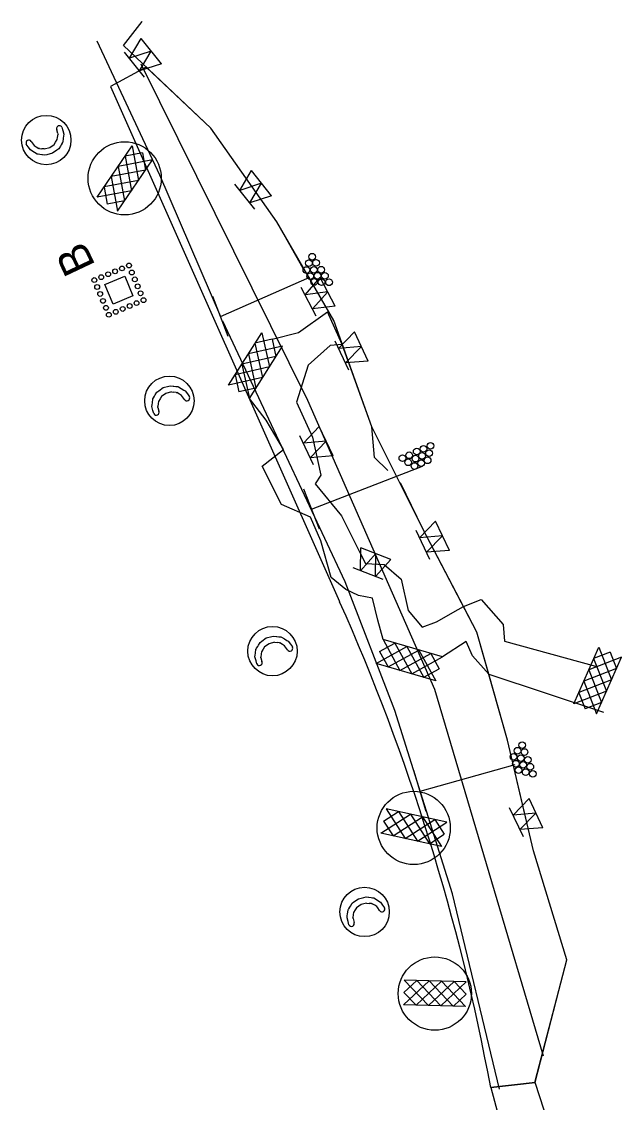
# Model space of a CAD drawing. Extents: x 400935 to 481562, y 415700 to 505362.
# Drawn here: x 477725 to 478005, y 499056 to 499559 of the extents above; entities that cross this region are included whole.
import ezdxf

# ---------------------------------------------------------------- set-up
doc = ezdxf.new("R2010")
doc.units = 0
for name, color, linetype in [('Coir Fiber Wattle with PAM Final CELL', 7, 'Continuous'), ('Drain Terminator Final CELL', 7, 'Continuous'), ('Earth Berm for Slope Drains Final', 7, 'Continuous'), ('Excelsior Wattle Line Style Final', 7, 'Continuous'), ('Label B Final CELL', 7, 'Continuous'), ('Matting on Slope Note Final CELL', 7, 'Continuous'), ('Rock Inlet Sediment Trap Type B Final CELL', 7, 'Continuous'), ('Rock Silt Check Type A CG CELL', 7, 'Continuous'), ('Rock Silt Check Type A Final CELL', 7, 'Continuous'), ('Rock Silt Check Type A with Matting and PAM CG CELL', 7, 'Continuous'), ('Slope Drain Final', 7, 'Continuous'), ('Slope Drain Inlet Final CELL', 7, 'Continuous'), ('Special Sediment Control Fence Section Both CELL', 7, 'Continuous'), ('Special Sediment Control Fence Section CG CELL', 7, 'Continuous'), ('Special Sediment Control Fence Section Final CELL', 7, 'Continuous'), ('Temporary Silt Fence Both', 7, 'Continuous'), ('Temporary Silt Fence CG', 7, 'Continuous'), ('Temporary Silt Fence Final', 7, 'Continuous')]:
    doc.layers.add(name, color=color, linetype=linetype)

msp = doc.modelspace()

# ---------------------------------------------------------------- linework, layer by layer
at = {"layer": 'Coir Fiber Wattle with PAM Final CELL'}
for p, q in [((477742.19, 499507), (477741.72, 499508.8)), ((477742.08, 499505.21), (477742.27, 499506.68)), ((477742.19, 499507), (477742.27, 499506.68)), ((477729.81, 499503.34), (477730.71, 499502.08)), ((477730.71, 499502.08), (477731.17, 499501.44)), ((477738.42, 499500.51), (477740.51, 499501.97)), ((477740.51, 499501.97), (477741.16, 499502.98)), ((477741.16, 499502.98), (477741.94, 499504.2)), ((477741.94, 499504.2), (477742.08, 499505.21)), ((477731.17, 499501.44), (477732.11, 499500.86)), ((477732.11, 499500.86), (477733.35, 499500.11)), ((477733.59, 499500.08), (477733.35, 499500.11)), ((477733.59, 499500.08), (477734.69, 499499.95)), ((477735.87, 499499.82), (477734.69, 499499.95)), ((477735.87, 499499.82), (477738.41, 499500.51)), ((477738.42, 499500.51), (477738.41, 499500.51)), ((477792.52, 499386.1), (477790.43, 499384.64)), ((477792.52, 499386.1), (477792.53, 499386.1)), ((477795.06, 499386.79), (477792.53, 499386.1)), ((477795.06, 499386.79), (477796.25, 499386.66)), ((477797.35, 499386.53), (477796.25, 499386.66)), ((477797.35, 499386.53), (477797.58, 499386.5)), ((477798.83, 499385.75), (477797.58, 499386.5)), ((477788.86, 499381.4), (477788.67, 499379.93)), ((477788.99, 499382.41), (477788.86, 499381.4)), ((477789.78, 499383.63), (477788.99, 499382.41)), ((477790.43, 499384.64), (477789.78, 499383.63)), ((477799.77, 499385.17), (477798.83, 499385.75)), ((477800.23, 499384.53), (477799.77, 499385.17)), ((477801.13, 499383.27), (477800.23, 499384.53)), ((477788.75, 499379.61), (477788.67, 499379.93)), ((477788.75, 499379.61), (477789.22, 499377.8)), ((477843.06, 499270.32), (477840.52, 499269.63)), ((477843.06, 499270.32), (477844.25, 499270.19)), ((477836.99, 499265.94), (477836.86, 499264.93)), ((477837.78, 499267.16), (477836.99, 499265.94)), ((477838.43, 499268.17), (477837.78, 499267.16)), ((477840.51, 499269.63), (477838.43, 499268.17)), ((477840.51, 499269.63), (477840.52, 499269.63)), ((477845.35, 499270.06), (477844.25, 499270.19)), ((477845.35, 499270.06), (477845.58, 499270.03)), ((477846.82, 499269.28), (477845.58, 499270.03)), ((477847.77, 499268.7), (477846.82, 499269.28)), ((477848.23, 499268.06), (477847.77, 499268.7)), ((477849.13, 499266.8), (477848.23, 499268.06)), ((477836.86, 499264.93), (477836.67, 499263.46)), ((477836.75, 499263.14), (477836.67, 499263.46)), ((477836.75, 499263.14), (477837.22, 499261.34)), ((477880.64, 499145.82), (477879.86, 499144.61)), ((477881.3, 499146.83), (477880.64, 499145.82)), ((477883.38, 499148.29), (477881.3, 499146.83)), ((477883.38, 499148.29), (477883.39, 499148.29)), ((477885.93, 499148.98), (477883.39, 499148.29)), ((477885.93, 499148.98), (477887.11, 499148.85)), ((477888.22, 499148.72), (477887.11, 499148.85)), ((477888.22, 499148.72), (477888.45, 499148.69)), ((477889.69, 499147.94), (477888.45, 499148.69)), ((477890.63, 499147.37), (477889.69, 499147.94)), ((477891.09, 499146.72), (477890.63, 499147.37)), ((477891.99, 499145.46), (477891.09, 499146.72)), ((477879.72, 499143.59), (477879.53, 499142.12)), ((477879.62, 499141.8), (477879.53, 499142.12)), ((477879.62, 499141.8), (477880.08, 499140)), ((477879.86, 499144.61), (477879.72, 499143.59))]:
    msp.add_line(p, q, dxfattribs=at)
for points in [[(477744.07, 499509.91), (477744.48, 499508.41), (477744.96, 499506.66), (477744.86, 499505.83), (477744.73, 499504.83), (477744.5, 499503.05), (477744.48, 499503.01), (477744.25, 499502.64), (477744.21, 499502.57), (477743.71, 499501.76), (477743.36, 499501.19), (477742.6, 499499.94), (477741.75, 499499.33), (477739.69, 499497.83), (477739.68, 499497.82), (477737.13, 499497.16), (477736.13, 499496.91), (477735.01, 499497.07), (477734.78, 499497.1), (477733.82, 499497.24), (477733.1, 499497.34), (477732.93, 499497.37), (477732.57, 499497.42), (477732.56, 499497.42), (477731.28, 499498.22), (477730.14, 499498.93), (477729.45, 499499.36), (477728.41, 499500.78), (477727.5, 499502.03)], [(477786.87, 499376.7), (477786.46, 499378.2), (477785.97, 499379.95), (477786.08, 499380.78), (477786.21, 499381.78), (477786.44, 499383.56), (477786.46, 499383.6), (477786.69, 499383.97), (477786.73, 499384.04), (477787.23, 499384.85), (477787.57, 499385.42), (477788.34, 499386.67), (477789.18, 499387.28), (477791.25, 499388.78), (477791.26, 499388.79), (477793.81, 499389.45), (477794.81, 499389.7), (477795.93, 499389.54), (477796.16, 499389.51), (477797.11, 499389.37), (477797.84, 499389.27), (477798, 499389.24), (477798.37, 499389.19), (477798.38, 499389.19), (477799.66, 499388.39), (477800.8, 499387.68), (477801.48, 499387.25), (477802.52, 499385.83), (477803.44, 499384.58)], [(477834.87, 499260.23), (477834.45, 499261.73), (477833.97, 499263.48), (477834.08, 499264.31), (477834.21, 499265.31), (477834.43, 499267.09), (477834.45, 499267.13), (477834.69, 499267.5), (477834.72, 499267.57), (477835.22, 499268.38), (477835.57, 499268.95), (477836.34, 499270.2), (477837.18, 499270.81), (477839.24, 499272.31), (477839.25, 499272.32), (477841.81, 499272.98), (477842.8, 499273.23), (477843.92, 499273.07), (477844.16, 499273.04), (477845.11, 499272.9), (477845.83, 499272.8), (477846, 499272.77), (477846.37, 499272.72), (477846.37, 499272.72), (477847.66, 499271.92), (477848.8, 499271.21), (477849.48, 499270.78), (477850.52, 499269.36), (477851.44, 499268.12)], [(477877.73, 499138.89), (477877.32, 499140.39), (477876.84, 499142.14), (477876.94, 499142.97), (477877.07, 499143.98), (477877.3, 499145.75), (477877.32, 499145.79), (477877.55, 499146.17), (477877.59, 499146.23), (477878.09, 499147.05), (477878.44, 499147.61), (477879.21, 499148.86), (477880.05, 499149.48), (477882.11, 499150.97), (477882.12, 499150.98), (477884.67, 499151.64), (477885.67, 499151.9), (477886.79, 499151.74), (477887.03, 499151.7), (477887.98, 499151.56), (477888.7, 499151.46), (477888.87, 499151.43), (477889.23, 499151.38), (477889.24, 499151.38), (477890.52, 499150.58), (477891.66, 499149.87), (477892.35, 499149.44), (477893.39, 499148.03), (477894.31, 499146.78)]]:
    msp.add_lwpolyline(points, dxfattribs=at)
for centre in [(477736.81, 499503.96), (477794.13, 499382.65), (477842.12, 499266.18), (477884.99, 499144.85)]:
    msp.add_circle(centre, 11.5, dxfattribs=at)
for centre, radius, start, end in [((477742.89, 499509.36), 1.3, 25.2938, 205.2938), ((477728.7, 499502.6), 1.33, 34.1812, 205.2938), ((477802.23, 499384.01), 1.33, 214.1812, 25.2938), ((477788.04, 499377.25), 1.3, 205.2938, 25.2938), ((477850.23, 499267.54), 1.33, 214.1812, 25.2938), ((477836.04, 499260.78), 1.3, 205.2938, 25.2938), ((477893.1, 499146.21), 1.33, 214.1812, 25.2938), ((477878.91, 499139.44), 1.3, 205.2938, 25.2938)]:
    msp.add_arc(centre, radius, start, end, dxfattribs=at)
at = {"layer": 'Drain Terminator Final CELL'}
for centre in [(477859.1, 499446.68), (477860.57, 499449.7), (477862.38, 499446.83), (477857.89, 499443.5), (477859.71, 499440.63), (477861.36, 499443.61), (477863.11, 499440.85), (477864.72, 499443.64), (477866.54, 499440.77), (477861.57, 499437.95), (477865, 499437.87), (477868.43, 499437.79), (477912.41, 499360.35), (477915.67, 499361.69), (477902.58, 499356.01), (477905.72, 499357.3), (477908.72, 499355.74), (477909.26, 499359.06), (477911.73, 499356.99), (477914.33, 499354.97), (477915, 499358.33), (477905.3, 499354.04), (477908.22, 499352.31), (477911.36, 499353.6), (477956.23, 499219.85), (477958.33, 499222.46), (477959.46, 499219.26), (477954.33, 499217.03), (477955.46, 499213.82), (477957.74, 499216.35), (477961.02, 499215.63), (477956.67, 499210.79), (477958.82, 499213.27), (477959.99, 499209.94), (477962.14, 499212.42), (477963.31, 499209.09)]:
    msp.add_circle(centre, 1.55, dxfattribs=at)
at = {"layer": 'Earth Berm for Slope Drains Final'}
for points in [[(477760.4, 499550.06), (477789.53, 499487.76), (477817.9, 499421.86)], [(477947.85, 499062.34), (477925.9, 499153.21), (477899.15, 499238.55), (477875.99, 499298.44), (477838.06, 499379.1), (477818.98, 499419.67)]]:
    msp.add_lwpolyline(points, dxfattribs=at)
at = {"layer": 'Excelsior Wattle Line Style Final'}
msp.add_lwpolyline([(477968.25, 499077.76), (477917.71, 499248.4), (477858.51, 499382.83), (477781.01, 499539.35)], dxfattribs=at)
at = {"layer": 'Matting on Slope Note Final CELL'}
for p, q in [((477783.38, 499537.83), (477766.68, 499528.82)), ((477813.41, 499509.58), (477783.38, 499537.83)), ((477766.68, 499528.82), (477873.37, 499289.21)), ((477844.12, 499465.92), (477813.41, 499509.58)), ((477870.67, 499420.04), (477844.12, 499465.92)), ((477888.37, 499370.5), (477870.67, 499420.04)), ((477912.09, 499323.05), (477888.37, 499370.5)), ((477937.21, 499275.05), (477912.09, 499323.05)), ((477951.58, 499224.75), (477937.21, 499275.05)), ((477963.66, 499173.21), (477951.58, 499224.75)), ((477979.18, 499122.58), (477963.66, 499173.21)), ((477964.36, 499065.56), (477979.18, 499122.58)), ((477943.73, 499063.24), (477964.36, 499065.56))]:
    msp.add_line(p, q, dxfattribs=at)
msp.add_lwpolyline([(477978.88, 499021.21), (477964.36, 499065.56), (477943.73, 499063.24), (477950.63, 499037.67)], dxfattribs=at)
msp.add_arc((476947.96, 498877.15), 1013, 10.58498, 24.00169, dxfattribs=at)
at = {"layer": 'Rock Inlet Sediment Trap Type B Final CELL'}
msp.add_lwpolyline([(477767.95, 499427.61), (477764.08, 499436.83), (477773.3, 499440.7), (477777.16, 499431.47)], close=True, dxfattribs=at)
for centre in [(477775.3, 499445.6), (477762.39, 499440.18), (477765.61, 499441.54), (477768.84, 499442.89), (477772.07, 499444.24), (477776.65, 499442.37), (477759.16, 499438.83), (477760.51, 499435.6), (477778.01, 499439.14), (477779.36, 499435.92), (477761.87, 499432.37), (477780.71, 499432.69), (477763.22, 499429.14), (477764.58, 499425.92), (477772.39, 499425.4), (477775.61, 499426.75), (477778.84, 499428.11), (477782.07, 499429.46), (477765.93, 499422.69), (477769.16, 499424.04)]:
    msp.add_circle(centre, 1.12, dxfattribs=at)
at = {"layer": 'Rock Silt Check Type A CG CELL'}
for p, q in [((477821.6, 499389.93), (477837.09, 499414.33)), ((477841.95, 499411.26), (477833.97, 499409.44)), ((477837.09, 499414.33), (477840.65, 499398.39)), ((477841.95, 499411.26), (477843.73, 499403.24)), ((477846.84, 499408.14), (477830.9, 499404.58)), ((477831.35, 499383.74), (477846.84, 499408.14)), ((477833.97, 499409.44), (477837.54, 499393.49)), ((477843.73, 499403.24), (477827.79, 499399.68)), ((477830.9, 499404.58), (477834.43, 499388.6)), ((477840.65, 499398.39), (477824.68, 499394.79)), ((477827.79, 499399.68), (477831.35, 499383.74)), ((477837.54, 499393.49), (477821.6, 499389.93)), ((477824.7, 499394.72), (477826.45, 499386.84)), ((477834.43, 499388.6), (477826.45, 499386.84)), ((477893.58, 499271.55), (477901.44, 499257.23)), ((477921.33, 499263.47), (477893.58, 499271.55)), ((477890.35, 499260.46), (477904.67, 499268.32)), ((477891.95, 499265.98), (477899.15, 499269.93)), ((477891.95, 499265.98), (477895.92, 499258.83)), ((477895.92, 499258.83), (477910.24, 499266.7)), ((477899.15, 499269.93), (477907.01, 499255.61)), ((477904.67, 499268.32), (477912.58, 499253.99)), ((477910.24, 499266.7), (477918.1, 499252.38)), ((477918.1, 499252.38), (477890.35, 499260.46)), ((477901.44, 499257.23), (477915.81, 499265.08)), ((477907.01, 499255.61), (477921.33, 499263.47)), ((477915.81, 499265.08), (477919.72, 499257.9)), ((477912.64, 499254.02), (477919.72, 499257.9))]:
    msp.add_line(p, q, dxfattribs=at)
at = {"layer": 'Rock Silt Check Type A Final CELL'}
for p, q in [((477982.35, 499241.62), (477993.98, 499268.07)), ((477999.25, 499265.77), (477991.63, 499262.77)), ((477993.98, 499268.07), (477999.9, 499252.85)), ((477999.25, 499265.77), (478002.22, 499258.12)), ((478004.55, 499263.42), (477989.33, 499257.5)), ((477991.63, 499262.77), (477997.57, 499247.54)), ((477992.92, 499236.97), (478004.55, 499263.42)), ((478002.22, 499258.12), (477987, 499252.19)), ((477989.33, 499257.5), (477995.23, 499242.23)), ((477999.9, 499252.85), (477984.66, 499246.88)), ((477987, 499252.19), (477992.92, 499236.97)), ((477997.57, 499247.54), (477982.35, 499241.62)), ((477984.69, 499246.82), (477987.61, 499239.29)), ((477995.23, 499242.23), (477987.61, 499239.29))]:
    msp.add_line(p, q, dxfattribs=at)
at = {"layer": 'Rock Silt Check Type A with Matting and PAM CG CELL'}
for p, q in [((477760.45, 499477.41), (477776.8, 499501.24)), ((477781.55, 499498), (477773.51, 499496.47)), ((477776.8, 499501.24), (477779.79, 499485.18)), ((477781.55, 499498), (477783.04, 499489.92)), ((477769.97, 499470.88), (477786.33, 499494.7)), ((477786.33, 499494.7), (477770.27, 499491.72)), ((477770.27, 499491.72), (477773.22, 499475.62)), ((477773.51, 499496.47), (477776.51, 499480.4)), ((477783.04, 499489.92), (477766.98, 499486.94)), ((477766.98, 499486.94), (477769.97, 499470.88)), ((477779.79, 499485.18), (477763.7, 499482.15)), ((477763.72, 499482.09), (477765.18, 499474.15)), ((477776.51, 499480.4), (477760.45, 499477.41)), ((477773.22, 499475.62), (477765.18, 499474.15)), ((477892.6, 499181.46), (477906.33, 499190.3)), ((477893.8, 499187.08), (477900.71, 499191.52)), ((477895.04, 499192.75), (477903.88, 499179.01)), ((477923.29, 499186.63), (477895.04, 499192.75)), ((477900.71, 499191.52), (477909.55, 499177.78)), ((477906.33, 499190.3), (477915.22, 499176.56)), ((477893.8, 499187.08), (477898.26, 499180.22)), ((477898.26, 499180.22), (477912, 499189.07)), ((477903.88, 499179.01), (477917.67, 499187.84)), ((477909.55, 499177.78), (477923.29, 499186.63)), ((477912, 499189.07), (477920.84, 499175.34)), ((477917.67, 499187.84), (477922.07, 499180.96)), ((477920.84, 499175.34), (477892.6, 499181.46)), ((477915.28, 499176.59), (477922.07, 499180.96)), ((477903.14, 499101.64), (477915.02, 499112.84)), ((477903.29, 499107.38), (477909.27, 499113.01)), ((477903.48, 499113.18), (477914.68, 499101.3)), ((477932.36, 499112.34), (477903.48, 499113.18)), ((477908.94, 499101.45), (477920.82, 499112.68)), ((477909.27, 499113.01), (477920.48, 499101.13)), ((477914.68, 499101.3), (477926.62, 499112.51)), ((477915.02, 499112.84), (477926.28, 499100.96)), ((477920.48, 499101.13), (477932.36, 499112.34)), ((477920.82, 499112.68), (477932.03, 499100.79)), ((477926.62, 499112.51), (477932.21, 499106.54)), ((477903.29, 499107.38), (477908.94, 499101.45)), ((477926.33, 499101.01), (477932.21, 499106.54)), ((477932.03, 499100.79), (477903.14, 499101.64))]:
    msp.add_line(p, q, dxfattribs=at)
for centre in [(477773.31, 499486.17), (477907.87, 499183.93), (477917.7, 499106.86)]:
    msp.add_circle(centre, 17.04, dxfattribs=at)
at = {"layer": 'Slope Drain Final'}
for p, q in [((477817.9, 499421.86), (477859.48, 499440.12)), ((477860.34, 499332.19), (477911.95, 499352.17)), ((477910.86, 499201.11), (477955.11, 499213.46))]:
    msp.add_line(p, q, dxfattribs=at)
at = {"layer": 'Slope Drain Inlet Final CELL'}
for p, q in [((477821.49, 499412.53), (477814.31, 499431.19)), ((477863.93, 499322.86), (477856.75, 499341.52)), ((477913.73, 499191.53), (477907.99, 499210.69))]:
    msp.add_line(p, q, dxfattribs=at)
at = {"layer": 'Special Sediment Control Fence Section Both CELL'}
for p, q in [((477790.4, 499539.48), (477781.02, 499551.19)), ((477782.6, 499533.23), (477773.22, 499544.94)), ((477841.71, 499478.03), (477832.34, 499489.75)), ((477833.9, 499471.79), (477824.54, 499483.5)), ((477871.36, 499426.75), (477864.35, 499440.01)), ((477862.52, 499422.07), (477855.51, 499435.33)), ((477967.95, 499184.03), (477961.54, 499197.59)), ((477958.9, 499179.75), (477952.5, 499193.32))]:
    msp.add_line(p, q, dxfattribs=at)
for points in [[(477785.71, 499545.34), (477775.56, 499542.01), (477781.02, 499551.19)], [(477790.4, 499539.48), (477780.25, 499536.16), (477785.71, 499545.34)], [(477837.03, 499483.89), (477826.88, 499480.57), (477832.34, 499489.75)], [(477841.71, 499478.03), (477831.56, 499474.71), (477837.03, 499483.89)], [(477867.85, 499433.38), (477857.26, 499432.02), (477864.35, 499440.01)], [(477871.36, 499426.75), (477860.77, 499425.39), (477867.85, 499433.38)], [(477964.74, 499190.81), (477954.1, 499189.93), (477961.54, 499197.59)], [(477967.95, 499184.03), (477957.3, 499183.15), (477964.74, 499190.81)]]:
    msp.add_lwpolyline(points, dxfattribs=at)
at = {"layer": 'Special Sediment Control Fence Section CG CELL'}
for p, q in [((477861.28, 499352.79), (477854.87, 499366.35)), ((477870.32, 499357.06), (477863.91, 499370.63)), ((477897.21, 499308.88), (477883.23, 499314.3)), ((477893.6, 499299.56), (477879.61, 499304.98))]:
    msp.add_line(p, q, dxfattribs=at)
for points in [[(477867.12, 499363.84), (477856.48, 499362.96), (477863.91, 499370.63)], [(477870.32, 499357.06), (477859.68, 499356.18), (477867.12, 499363.84)], [(477890.22, 499311.59), (477883.11, 499303.62), (477883.23, 499314.3)], [(477897.21, 499308.88), (477890.1, 499300.91), (477890.22, 499311.59)]]:
    msp.add_lwpolyline(points, dxfattribs=at)
at = {"layer": 'Special Sediment Control Fence Section Final CELL'}
for p, q in [((477886.73, 499401.14), (477880.32, 499414.7)), ((477877.69, 499396.87), (477871.28, 499410.43)), ((477924.45, 499313.04), (477918.04, 499326.6)), ((477915.41, 499308.77), (477909, 499322.33))]:
    msp.add_line(p, q, dxfattribs=at)
for points in [[(477883.53, 499407.92), (477872.88, 499407.04), (477880.32, 499414.7)], [(477886.73, 499401.14), (477876.09, 499400.26), (477883.53, 499407.92)], [(477921.25, 499319.82), (477910.6, 499318.94), (477918.04, 499326.6)], [(477924.45, 499313.04), (477913.81, 499312.16), (477921.25, 499319.82)]]:
    msp.add_lwpolyline(points, dxfattribs=at)
at = {"layer": 'Temporary Silt Fence Both'}
for p, q in [((477951.58, 499224.75), (477942.9, 499255.45)), ((477963.66, 499173.21), (477956.08, 499205.57)), ((477979.18, 499122.58), (477963.66, 499173.21)), ((477964.44, 499066.16), (477979.18, 499122.58)), ((477964.27, 499065.2), (477964.44, 499066.16))]:
    msp.add_line(p, q, dxfattribs=at)
msp.add_lwpolyline([(477856.34, 499444.28), (477844.12, 499465.92), (477813.41, 499509.58), (477772.68, 499547.89), (477781.48, 499559.08), (477781.48, 499559.08)], dxfattribs=at)
at = {"layer": 'Temporary Silt Fence CG'}
msp.add_line((477942.9, 499255.45), (477996.2, 499237.76), dxfattribs=at)
for points in [[(477841.95, 499411.26), (477841.95, 499411.26), (477854.3, 499414.42), (477867.74, 499424.09)], [(477874.58, 499408.85), (477868.96, 499408.44), (477858.66, 499399.27), (477853.23, 499382.08), (477860.75, 499365.69), (477864.59, 499348.07), (477861.94, 499344.04), (477874.2, 499329.09), (477882.94, 499311.84), (477885.4, 499307), (477894.13, 499306.43), (477902.04, 499299.6), (477905.29, 499285.16), (477911.78, 499277.41), (477918.55, 499279.75), (477928.63, 499285.49), (477931.09, 499286.9)], [(477893.58, 499271.55), (477893.58, 499271.55), (477891.1, 499280.66), (477888.69, 499290.79), (477882.2, 499292.03), (477876.21, 499294.82), (477869.5, 499300.41), (477864.68, 499317.57), (477859.85, 499328.56), (477846.26, 499334.43), (477837.26, 499352.17), (477847.18, 499360.06), (477839.16, 499373.7), (477831.35, 499383.74)], [(477931.09, 499286.9), (477939.22, 499290.14), (477949.57, 499278.63), (477950.15, 499270.85), (477992.43, 499259.21)], [(477942.9, 499255.45), (477935.18, 499263.97), (477932.25, 499270.7), (477921.33, 499263.47), (477921.33, 499263.47), (477921.33, 499263.47)]]:
    msp.add_lwpolyline(points, dxfattribs=at)
at = {"layer": 'Temporary Silt Fence Final'}
for p, q in [((477874.58, 499408.85), (477867.74, 499424.09)), ((477888.37, 499370.5), (477874.58, 499408.85)), ((477889.6, 499356.28), (477888.37, 499370.5)), ((477895.76, 499350.24), (477889.6, 499356.28)), ((477912.09, 499323.05), (477901.66, 499344.45)), ((477931.09, 499286.9), (477912.09, 499323.05))]:
    msp.add_line(p, q, dxfattribs=at)
msp.add_lwpolyline([(477942.9, 499255.45), (477937.21, 499275.05), (477931.09, 499286.9)], dxfattribs=at)

# ---------------------------------------------------------------- texts
at = {"layer": 'Label B Final CELL'}
msp.add_text('B', height=15, rotation=115.2938, dxfattribs=at).set_placement((477759.85, 499445.53))

doc.saveas('drawing.dxf')
